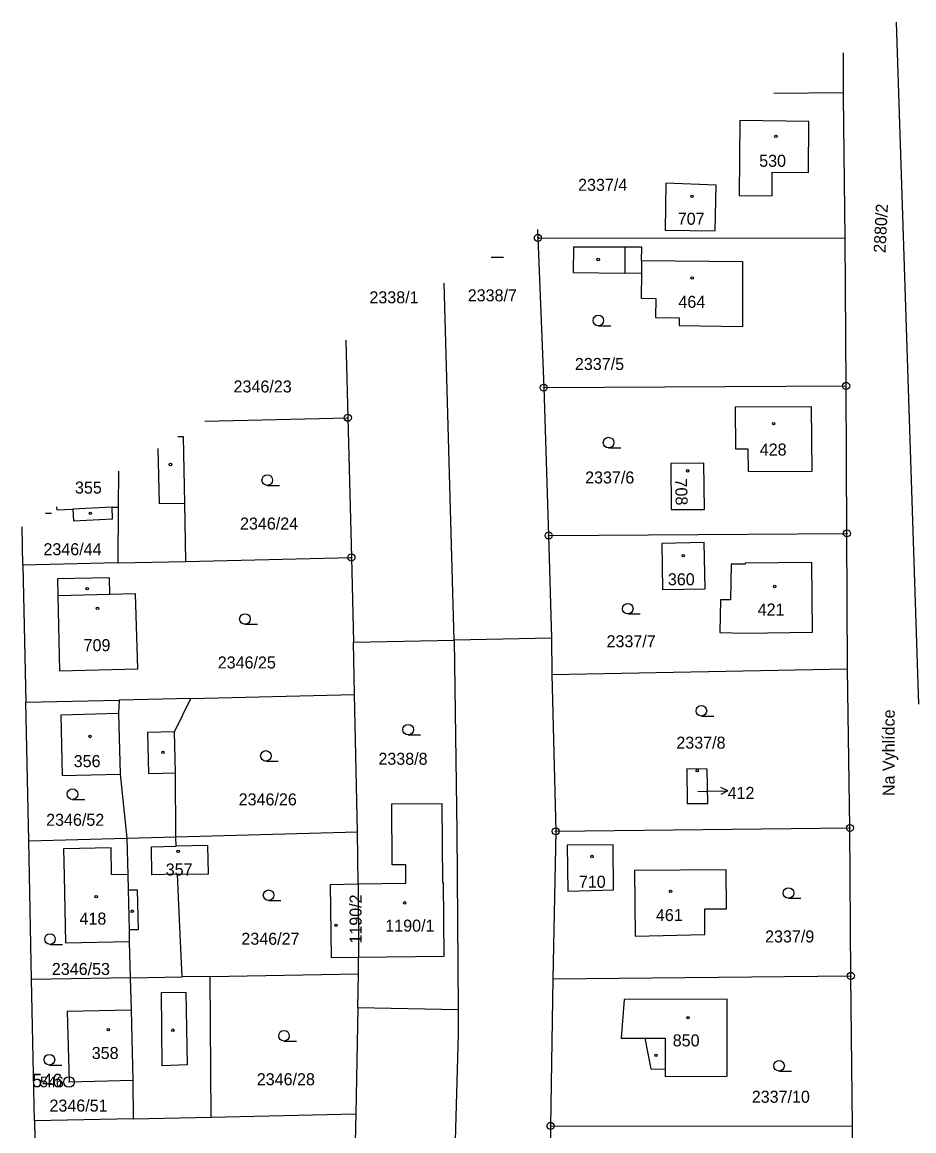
# Model space of a CAD drawing. Extents: x -758836 to -757729, y -1175316 to -1174366.
# Drawn here: x -758715.5 to -758589.5, y -1174868.1 to -1174711.3 of the extents above; entities that cross this region are included whole.
import ezdxf

# ---------------------------------------------------------------- set-up
doc = ezdxf.new("R2010")
doc.units = 0
for name, color, linetype in [('Hranice parcel', 7, 'Continuous'), ('Parcelní čísla', 7, 'Continuous'), ('Pop  PČ popisy', 7, 'Continuous'), ('Vnitřní kresba', 7, 'Continuous'), ('Značky bodu BP', 7, 'Continuous'), ('Značky budov', 7, 'Continuous'), ('Značky kultur', 7, 'Continuous')]:
    doc.layers.add(name, color=color, linetype=linetype)

msp = doc.modelspace()

# ---------------------------------------------------------------- linework, layer by layer
at = {"layer": 'Hranice parcel'}
for p, q in [((-758588.72, -1174807.72), (-758591.88, -1174711.27)), ((-758599.38, -1174721.23), (-758599.41, -1174715.61)), ((-758609.26, -1174721.3), (-758599.38, -1174721.23)), ((-758642.64, -1174740.57), (-758642.59, -1174741.77)), ((-758642.59, -1174741.77), (-758641.77, -1174762.95)), ((-758599.02, -1174762.71), (-758599.18, -1174741.82)), ((-758654.45, -1174798.66), (-758655.86, -1174748.2)), ((-758669.76, -1174756.22), (-758669.46, -1174767.22)), ((-758641.77, -1174762.95), (-758599.02, -1174762.71)), ((-758598.91, -1174783.57), (-758599.02, -1174762.71)), ((-758641.77, -1174762.95), (-758641.07, -1174783.86)), ((-758689.66, -1174767.71), (-758669.46, -1174767.22)), ((-758669.46, -1174767.22), (-758668.95, -1174786.98)), ((-758715.38, -1174788.07), (-758715.49, -1174782.63)), ((-758641.07, -1174783.86), (-758640.69, -1174798.38)), ((-758598.81, -1174802.72), (-758598.91, -1174783.57)), ((-758701.96, -1174787.75), (-758715.38, -1174788.07)), ((-758701.96, -1174787.75), (-758692.34, -1174787.53)), ((-758692.34, -1174787.53), (-758668.95, -1174786.98)), ((-758668.95, -1174786.98), (-758668.68, -1174798.94)), ((-758715.38, -1174788.07), (-758714.98, -1174807.46)), ((-758668.68, -1174798.94), (-758654.45, -1174798.66)), ((-758668.51, -1174806.38), (-758668.68, -1174798.94)), ((-758640.69, -1174798.38), (-758654.45, -1174798.66)), ((-758640.69, -1174798.38), (-758640.6, -1174803.53)), ((-758640.6, -1174803.53), (-758598.81, -1174802.72)), ((-758640.6, -1174803.53), (-758640.07, -1174825.71)), ((-758598.48, -1174825.23), (-758598.81, -1174802.72)), ((-758691.67, -1174806.92), (-758668.51, -1174806.38)), ((-758668.07, -1174825.76), (-758668.51, -1174806.38)), ((-758714.98, -1174807.46), (-758701.78, -1174807.15)), ((-758714.57, -1174827.05), (-758714.98, -1174807.46)), ((-758691.67, -1174806.92), (-758701.78, -1174807.15)), ((-758640.07, -1174825.71), (-758598.48, -1174825.23)), ((-758598.36, -1174846.16), (-758598.48, -1174825.23)), ((-758714.57, -1174827.05), (-758700.68, -1174826.66)), ((-758714.17, -1174846.68), (-758714.57, -1174827.05)), ((-758700.68, -1174826.66), (-758693.78, -1174826.47)), ((-758700.68, -1174826.66), (-758700.57, -1174831.84)), ((-758693.78, -1174826.47), (-758668.07, -1174825.76)), ((-758668.02, -1174833.15), (-758668.07, -1174825.76)), ((-758640.07, -1174825.71), (-758640.49, -1174846.58)), ((-758668.02, -1174833.15), (-758667.95, -1174843.55)), ((-758700.36, -1174841.27), (-758700.21, -1174846.44)), ((-758667.93, -1174845.88), (-758667.95, -1174843.55)), ((-758688.92, -1174846.24), (-758667.93, -1174845.88)), ((-758668.03, -1174850.66), (-758667.93, -1174845.88)), ((-758700.21, -1174846.44), (-758714.17, -1174846.68)), ((-758713.75, -1174866.68), (-758714.17, -1174846.68)), ((-758700.21, -1174846.44), (-758692.87, -1174846.31)), ((-758688.92, -1174846.24), (-758692.87, -1174846.31)), ((-758688.8, -1174866.12), (-758688.92, -1174846.24)), ((-758640.49, -1174846.58), (-758640.8, -1174867.37)), ((-758640.49, -1174846.58), (-758598.36, -1174846.16)), ((-758598.14, -1174867.4), (-758598.36, -1174846.16)), ((-758668.03, -1174850.66), (-758668.33, -1174865.66)), ((-758653.88, -1174850.95), (-758668.03, -1174850.66)), ((-758699.8, -1174866.37), (-758713.75, -1174866.68)), ((-758699.8, -1174866.37), (-758688.8, -1174866.12)), ((-758688.8, -1174866.12), (-758668.33, -1174865.66)), ((-758668.33, -1174865.66), (-758668.75, -1174886.35)), ((-758713.75, -1174866.68), (-758713.31, -1174887.37)), ((-758640.8, -1174867.37), (-758641.04, -1174889.13)), ((-758640.8, -1174867.37), (-758598.14, -1174867.4)), ((-758598.11, -1174888.49), (-758598.14, -1174867.4))]:
    msp.add_line(p, q, dxfattribs=at)
for points in [[(-758599.18, -1174741.82), (-758599.37, -1174721.78), (-758599.38, -1174721.23)], [(-758604.27, -1174725.3), (-758614.03, -1174725.19), (-758614.14, -1174735.79), (-758609.49, -1174735.83), (-758609.46, -1174732.48), (-758604.36, -1174732.53), (-758604.27, -1174725.3)], [(-758624.49, -1174734.02), (-758624.61, -1174740.67), (-758617.52, -1174740.79), (-758617.41, -1174734.3), (-758624.49, -1174734.02)], [(-758642.59, -1174741.77), (-758642.29, -1174741.76), (-758599.18, -1174741.82)], [(-758613.6, -1174754.32), (-758613.6, -1174745.16), (-758627.93, -1174745.02), (-758627.91, -1174743.11), (-758630.32, -1174743.1), (-758637.54, -1174743.1), (-758637.59, -1174746.68), (-758630.32, -1174746.76), (-758627.95, -1174746.7), (-758627.98, -1174750.32), (-758625.91, -1174750.36), (-758625.95, -1174753.02), (-758622.61, -1174753.09), (-758622.63, -1174754.16), (-758613.6, -1174754.32)], [(-758612.89, -1174774.8), (-758603.8, -1174774.79), (-758603.93, -1174765.66), (-758614.69, -1174765.74), (-758614.65, -1174771.61), (-758612.92, -1174771.6), (-758612.89, -1174774.8)], [(-758692.34, -1174787.53), (-758692.5, -1174779.28), (-758692.68, -1174769.9), (-758693.47, -1174769.92)], [(-758619.04, -1174780.18), (-758619.12, -1174773.64), (-758623.79, -1174773.67), (-758623.74, -1174780.21), (-758619.04, -1174780.18)], [(-758710.62, -1174779.82), (-758710.61, -1174780.23), (-758708.31, -1174780.13), (-758708.23, -1174781.78), (-758702.72, -1174781.53), (-758702.79, -1174779.88), (-758701.92, -1174779.84), (-758701.96, -1174787.75)], [(-758641.07, -1174783.86), (-758640.95, -1174783.86), (-758598.91, -1174783.57)], [(-758618.97, -1174791.39), (-758619.1, -1174784.86), (-758625.08, -1174784.99), (-758624.97, -1174791.52), (-758618.97, -1174791.39)], [(-758615.37, -1174792.99), (-758616.78, -1174792.96), (-758616.87, -1174797.6), (-758613.34, -1174797.67), (-758603.78, -1174797.55), (-758603.87, -1174787.67), (-758613.28, -1174787.76), (-758613.28, -1174787.93), (-758615.27, -1174787.92), (-758615.37, -1174792.99)], [(-758710.45, -1174792.4), (-758710.2, -1174803), (-758699.16, -1174802.74), (-758699.46, -1174792.14), (-758703.11, -1174792.23), (-758703.16, -1174789.85), (-758710.5, -1174790.02), (-758710.45, -1174792.4)], [(-758654.45, -1174798.66), (-758654.07, -1174825.73), (-758653.88, -1174850.95)], [(-758701.78, -1174807.15), (-758701.86, -1174809.05), (-758710.01, -1174809.26), (-758709.85, -1174817.8), (-758701.65, -1174817.61), (-758700.68, -1174826.66)], [(-758693.78, -1174826.47), (-758693.81, -1174817.42), (-758693.95, -1174811.63), (-758691.67, -1174806.92)], [(-758621.53, -1174816.89), (-758621.47, -1174821.77), (-758618.59, -1174821.78), (-758618.65, -1174816.91), (-758621.53, -1174816.89)], [(-758668.02, -1174833.15), (-758661.26, -1174833.02), (-758661.28, -1174830.45), (-758663.17, -1174830.46), (-758663.26, -1174821.84), (-758656.17, -1174821.78), (-758656.07, -1174832.96), (-758655.97, -1174832.96), (-758655.91, -1174843.41), (-758667.95, -1174843.55)], [(-758692.87, -1174846.31), (-758692.96, -1174844.31), (-758693.34, -1174836.15), (-758693.54, -1174831.79), (-758689.17, -1174831.71), (-758689.27, -1174827.71), (-758693.72, -1174827.81), (-758693.78, -1174826.47)], [(-758700.57, -1174831.84), (-758702.86, -1174831.83), (-758702.9, -1174828.05), (-758709.67, -1174828.17), (-758709.58, -1174831.99), (-758709.35, -1174841.49), (-758700.36, -1174841.27)], [(-758638.37, -1174834.15), (-758631.89, -1174833.99), (-758631.97, -1174827.62), (-758638.45, -1174827.69), (-758638.37, -1174834.15)], [(-758700.57, -1174831.84), (-758700.52, -1174834), (-758699.25, -1174833.97), (-758699.12, -1174839.63), (-758700.39, -1174839.66), (-758700.36, -1174841.27)], [(-758618.99, -1174840.3), (-758619, -1174836.67), (-758615.94, -1174836.65), (-758615.98, -1174831.16), (-758628.92, -1174831.24), (-758628.86, -1174840.52), (-758618.99, -1174840.3)], [(-758667.95, -1174843.55), (-758671.78, -1174843.59), (-758671.9, -1174833.22), (-758668.02, -1174833.15)], [(-758700.21, -1174846.44), (-758700.11, -1174851), (-758709.12, -1174851.17), (-758708.87, -1174861.16), (-758699.84, -1174860.91), (-758699.8, -1174866.37)], [(-758615.85, -1174849.44), (-758630.38, -1174849.48), (-758630.81, -1174854.98), (-758627.47, -1174854.97), (-758626.62, -1174859.3), (-758624.58, -1174859.36), (-758624.58, -1174860.37), (-758615.82, -1174860.34), (-758615.85, -1174849.44)], [(-758653.88, -1174850.95), (-758653.85, -1174854.4), (-758655.65, -1174917.85)]]:
    msp.add_lwpolyline(points, dxfattribs=at)
at = {"layer": 'Pop  PČ popisy'}
for p, q in [((-758619.98, -1174820.07), (-758618.73, -1174820.04)), ((-758618.73, -1174820.04), (-758615.73, -1174819.99)), ((-758615.73, -1174819.99), (-758616.74, -1174819.5)), ((-758615.73, -1174819.99), (-758616.72, -1174820.51))]:
    msp.add_line(p, q, dxfattribs=at)
at = {"layer": 'Vnitřní kresba'}
for p, q in [((-758630.32, -1174743.1), (-758630.32, -1174746.76)), ((-758627.93, -1174745.02), (-758627.95, -1174746.7)), ((-758696.32, -1174771.56), (-758696.15, -1174779.36)), ((-758701.89, -1174774.78), (-758701.92, -1174779.84)), ((-758702.79, -1174779.88), (-758708.31, -1174780.13)), ((-758696.15, -1174779.36), (-758692.5, -1174779.28)), ((-758703.11, -1174792.23), (-758710.45, -1174792.4)), ((-758701.86, -1174809.05), (-758701.65, -1174817.61)), ((-758693.95, -1174811.63), (-758697.76, -1174811.75)), ((-758697.76, -1174811.75), (-758697.63, -1174817.51)), ((-758697.63, -1174817.51), (-758693.81, -1174817.42)), ((-758697.23, -1174827.89), (-758693.72, -1174827.81)), ((-758697.15, -1174831.85), (-758697.23, -1174827.89)), ((-758693.54, -1174831.79), (-758697.15, -1174831.85)), ((-758700.52, -1174834), (-758700.39, -1174839.66)), ((-758695.81, -1174848.52), (-758692.36, -1174848.44)), ((-758695.71, -1174858.88), (-758695.81, -1174848.52)), ((-758692.36, -1174848.44), (-758692.15, -1174858.75)), ((-758700.11, -1174851), (-758699.84, -1174860.91)), ((-758627.47, -1174854.97), (-758624.6, -1174854.96)), ((-758624.6, -1174854.96), (-758624.58, -1174859.36)), ((-758692.15, -1174858.75), (-758695.71, -1174858.88))]:
    msp.add_line(p, q, dxfattribs=at)
at = {"layer": 'Značky bodu BP'}
for centre, radius in [((-758642.59, -1174741.77), 0.5), ((-758642.59, -1174741.77), 0.0303), ((-758641.77, -1174762.95), 0.5), ((-758641.77, -1174762.95), 0.0303), ((-758599.02, -1174762.71), 0.5), ((-758599.02, -1174762.71), 0.0303), ((-758669.46, -1174767.22), 0.5), ((-758669.46, -1174767.22), 0.0303), ((-758598.91, -1174783.57), 0.5), ((-758641.07, -1174783.86), 0.5), ((-758641.07, -1174783.86), 0.0303), ((-758598.91, -1174783.57), 0.0303), ((-758668.95, -1174786.98), 0.5), ((-758668.95, -1174786.98), 0.0303), ((-758640.07, -1174825.71), 0.5), ((-758598.48, -1174825.23), 0.5), ((-758598.48, -1174825.23), 0.0303), ((-758640.07, -1174825.71), 0.0303), ((-758598.36, -1174846.16), 0.5), ((-758598.36, -1174846.16), 0.0303), ((-758708.87, -1174861.16), 0.75), ((-758708.87, -1174861.16), 0.03), ((-758640.8, -1174867.37), 0.5), ((-758640.8, -1174867.37), 0.0303)]:
    msp.add_circle(centre, radius, dxfattribs=at)
at = {"layer": 'Značky budov'}
for centre in [(-758608.95, -1174727.41), (-758620.81, -1174735.89), (-758634.07, -1174744.83), (-758620.79, -1174747.44), (-758609.27, -1174768.04), (-758694.53, -1174773.83), (-758621.43, -1174774.72), (-758705.86, -1174780.74), (-758622.04, -1174786.71), (-758609.12, -1174791.08), (-758706.31, -1174791.39), (-758704.85, -1174794.18), (-758705.9, -1174812.29), (-758695.59, -1174814.53), (-758620.07, -1174817.13), (-758693.44, -1174828.55), (-758634.95, -1174829.27), (-758705.03, -1174834.95), (-758623.84, -1174834.19), (-758661.42, -1174835.83), (-758699.94, -1174837.01), (-758671.12, -1174839), (-758621.37, -1174852.06), (-758703.32, -1174853.77), (-758694.19, -1174853.84), (-758625.91, -1174857.39)]:
    msp.add_circle(centre, 0.175, dxfattribs=at)
at = {"layer": 'Značky kultur'}
for p, q in [((-758649.19, -1174744.5), (-758647.44, -1174744.5)), ((-758634.05, -1174754.21), (-758632.3, -1174754.21)), ((-758632.6, -1174771.48), (-758630.85, -1174771.48)), ((-758680.85, -1174776.78), (-758679.1, -1174776.78)), ((-758712.18, -1174780.72), (-758711.36, -1174780.72)), ((-758629.89, -1174794.97), (-758628.14, -1174794.97)), ((-758684, -1174796.43), (-758682.25, -1174796.43)), ((-758619.48, -1174809.41), (-758617.73, -1174809.41)), ((-758660.93, -1174812.08), (-758659.18, -1174812.08)), ((-758681.04, -1174815.79), (-758679.29, -1174815.79)), ((-758708.38, -1174821.21), (-758706.63, -1174821.21)), ((-758680.66, -1174835.5), (-758678.91, -1174835.5)), ((-758607.17, -1174835.18), (-758605.42, -1174835.18)), ((-758711.56, -1174841.7), (-758709.81, -1174841.7)), ((-758678.48, -1174855.37), (-758676.73, -1174855.37)), ((-758711.65, -1174858.76), (-758709.9, -1174858.76)), ((-758608.5, -1174859.62), (-758606.75, -1174859.62))]:
    msp.add_line(p, q, dxfattribs=at)
for centre in [(-758634.05, -1174753.46), (-758632.6, -1174770.73), (-758680.85, -1174776.03), (-758629.89, -1174794.22), (-758684, -1174795.68), (-758619.48, -1174808.66), (-758660.93, -1174811.33), (-758681.04, -1174815.04), (-758708.38, -1174820.46), (-758680.66, -1174834.75), (-758607.17, -1174834.43), (-758711.56, -1174840.95), (-758678.48, -1174854.62), (-758711.65, -1174858.01), (-758608.5, -1174858.87)]:
    msp.add_circle(centre, 0.75, dxfattribs=at)

# ---------------------------------------------------------------- texts
at = {"layer": 'Parcelní čísla'}
for s, p in [('530', (-758611.31, -1174731.72)), ('2337/4', (-758636.91, -1174735.12)), ('707', (-758622.82, -1174739.92)), ('2338/1', (-758666.41, -1174751.03)), ('2338/7', (-758652.51, -1174750.75)), ('464', (-758622.73, -1174751.67)), ('2337/5', (-758637.36, -1174760.46)), ('2346/23', (-758685.61, -1174763.64)), ('428', (-758611.23, -1174772.56)), ('2337/6', (-758635.92, -1174776.51)), ('355', (-758708.03, -1174777.94)), ('2346/24', (-758684.7, -1174783.03)), ('2346/44', (-758712.49, -1174786.66)), ('360', (-758624.22, -1174790.91)), ('421', (-758611.52, -1174795.19)), ('709', (-758706.81, -1174800.23)), ('2337/7', (-758632.89, -1174799.68)), ('2346/25', (-758687.85, -1174802.68)), ('2337/8', (-758623.02, -1174814.02)), ('2338/8', (-758665.14, -1174816.3)), ('356', (-758708.21, -1174816.63)), ('2346/26', (-758684.89, -1174822.04)), ('412', (-758615.77, -1174821.12)), ('2346/52', (-758712.11, -1174824.93)), ('357', (-758695.2, -1174831.96)), ('710', (-758636.8, -1174833.69)), ('418', (-758707.39, -1174838.9)), ('1190/1', (-758664.16, -1174839.9)), ('461', (-758625.91, -1174838.4)), ('2337/9', (-758610.48, -1174841.43)), ('2346/27', (-758684.51, -1174841.75)), ('2346/53', (-758711.3, -1174846.03)), ('850', (-758623.53, -1174856.13)), ('358', (-758705.66, -1174857.91)), ('2346/28', (-758682.33, -1174861.62)), ('2337/10', (-758612.36, -1174864.1)), ('2346/51', (-758711.64, -1174865.35))]:
    msp.add_text(s, height=1.7, dxfattribs=at).set_placement(p)
for s, rotation, p in [('2880/2', 87, (-758593.46, -1174743.94)), ('708', 272, (-758623.23, -1174775.84)), ('1190/2', 90, (-758667.51, -1174841.59))]:
    msp.add_text(s, height=1.7, rotation=rotation, dxfattribs=at).set_placement(p)
at = {"layer": 'Pop  PČ popisy'}
msp.add_text('Na Vyhlídce', height=1.7, rotation=90, dxfattribs=at).set_placement((-758592.16, -1174820.73))
at = {"layer": 'Značky bodu BP'}
for height, p in [(1.919, (-758714.09, -1174861.91)), (1.5, (-758712.97, -1174861.91))]:
    msp.add_text('546', height=height, dxfattribs=at).set_placement(p)

doc.saveas('drawing.dxf')
